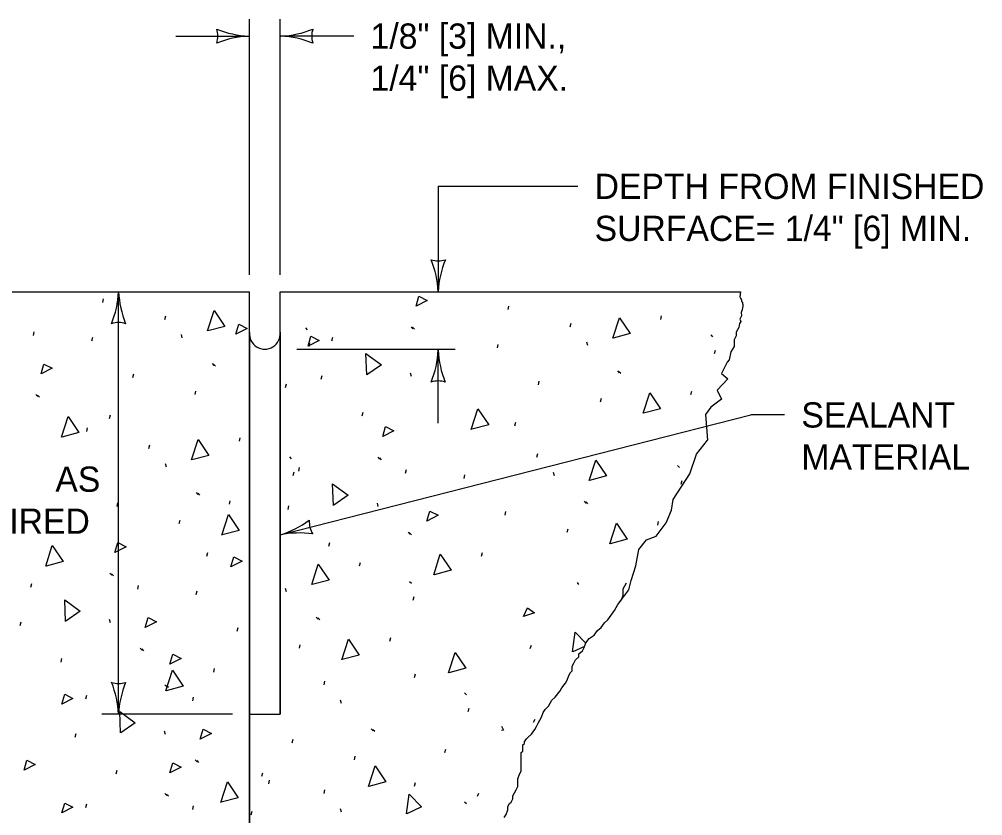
# Model space of a CAD drawing. Extents: x 49979.1 to 50021, y 49966.7 to 50011.4.
# Drawn here: x 50011.424 to 50013.716, y 49989.084 to 49990.977 of the extents above; entities that cross this region are included whole.
import ezdxf

# ---------------------------------------------------------------- set-up
doc = ezdxf.new("R2010")
doc.units = 0
for name, color, linetype in [('Level 1', 7, 'Continuous'), ('Level 12', 7, 'Continuous'), ('Level 13', 7, 'Continuous'), ('Level 2', 7, 'Continuous'), ('Level 3', 7, 'Continuous')]:
    doc.layers.add(name, color=color, linetype=linetype)

msp = doc.modelspace()

# ---------------------------------------------------------------- linework, layer by layer
at = {"layer": 'Level 1'}
for p, q in [((50010.8049, 49990.3296), (50011.972, 49990.3296)), ((50011.9717, 49989.3247), (50011.972, 49990.3296)), ((50012.0446, 49990.3296), (50013.1396, 49990.3296)), ((50012.0446, 49990.2334), (50012.0446, 49990.3296)), ((50011.972, 49990.2334), (50011.9714, 49988.4132)), ((50011.972, 49990.2334), (50011.972, 49990.2334)), ((50012.0446, 49989.3247), (50012.0446, 49990.2334)), ((50012.0446, 49990.2334), (50012.0446, 49989.3247))]:
    msp.add_line(p, q, dxfattribs=at)
for points in [[(50013.1396, 49990.3296), (50013.1383, 49990.3173), (50013.1403, 49990.3146), (50013.1403, 49990.3137), (50013.1413, 49990.3128), (50013.1413, 49990.3118), (50013.1413, 49990.3109), (50013.1424, 49990.31), (50013.1424, 49990.3091), (50013.1424, 49990.3082), (50013.1424, 49990.3073), (50013.1434, 49990.3054), (50013.1444, 49990.3045), (50013.1444, 49990.3036), (50013.1444, 49990.3027), (50013.1444, 49990.3018), (50013.1444, 49990.3008), (50013.1454, 49990.2999), (50013.1454, 49990.299), (50013.1454, 49990.2981), (50013.1454, 49990.2972), (50013.1454, 49990.2962), (50013.1454, 49990.2953), (50013.1437, 49990.2875), (50013.1437, 49990.2866), (50013.1427, 49990.2822), (50013.1414, 49990.2803), (50013.1427, 49990.272), (50013.1386, 49990.2641), (50013.1404, 49990.2586), (50013.1372, 49990.254), (50013.1363, 49990.2447), (50013.1298, 49990.2332), (50013.1298, 49990.2244), (50013.1252, 49990.2152), (50013.1252, 49990.199), (50013.1169, 49990.187), (50013.1132, 49990.1676), (50013.1081, 49990.162), (50013.095, 49990.1355), (50013.1099, 49990.1228), (50013.0843, 49990.0951), (50013.095, 49990.0738), (50013.0694, 49990.0547), (50013.0567, 49990.0376), (50013.0614, 49989.9766)], [(50012.6104, 49989.1712), (50012.6144, 49989.1823), (50012.6184, 49989.1896), (50012.6184, 49989.2006), (50012.6184, 49989.2116), (50012.6184, 49989.2226), (50012.6184, 49989.2263), (50012.6184, 49989.2336), (50012.6225, 49989.2373), (50012.6225, 49989.241), (50012.6225, 49989.2447), (50012.6225, 49989.2483), (50012.6225, 49989.252), (50012.6265, 49989.2557), (50012.6265, 49989.2593), (50012.6305, 49989.2667), (50012.6346, 49989.2704), (50012.6427, 49989.2777), (50012.6507, 49989.2887), (50012.6548, 49989.2961), (50012.6588, 49989.3034), (50012.6628, 49989.3107), (50012.6669, 49989.3181), (50012.6709, 49989.3291), (50012.675, 49989.3364), (50012.683, 49989.3438), (50012.6871, 49989.3511), (50012.6911, 49989.3585), (50012.6992, 49989.3658), (50012.7113, 49989.3805), (50012.7153, 49989.3878), (50012.7234, 49989.3988), (50012.7274, 49989.4062), (50012.7315, 49989.4172), (50012.7355, 49989.4245), (50012.7396, 49989.4282), (50012.7396, 49989.4319), (50012.7396, 49989.4392), (50012.7436, 49989.4466), (50012.7476, 49989.4539), (50012.7557, 49989.4612), (50012.7557, 49989.4686), (50012.7638, 49989.4759), (50012.7678, 49989.4833), (50012.7718, 49989.4943), (50012.7799, 49989.5053), (50012.792, 49989.5126), (50012.8001, 49989.5237), (50012.8082, 49989.531), (50012.8162, 49989.542), (50012.8243, 49989.5494), (50012.8324, 49989.5604), (50012.8405, 49989.5714), (50012.8485, 49989.5861), (50012.8743, 49989.6204), (50012.8799, 49989.6426), (50012.8909, 49989.6777), (50012.8983, 49989.7165), (50012.9162, 49989.7398), (50012.9396, 49989.7483), (50012.963, 49989.7802), (50012.9758, 49989.81), (50012.9801, 49989.8355), (50013.0194, 49989.8969), (50013.0353, 49989.9435), (50013.0614, 49989.9766)], [(50012.6104, 49989.1712), (50012.6144, 49989.1823), (50012.6184, 49989.1896), (50012.6184, 49989.2006), (50012.6184, 49989.2116), (50012.6184, 49989.2226), (50012.6184, 49989.2263), (50012.6184, 49989.2336), (50012.6225, 49989.2373), (50012.6225, 49989.241), (50012.6225, 49989.2447), (50012.6225, 49989.2483), (50012.6225, 49989.252), (50012.6265, 49989.2557), (50012.6265, 49989.2593), (50012.6305, 49989.2667), (50012.6346, 49989.2704), (50012.6427, 49989.2777), (50012.6507, 49989.2887), (50012.6548, 49989.2961), (50012.6588, 49989.3034), (50012.6628, 49989.3107), (50012.6669, 49989.3181), (50012.6709, 49989.3291), (50012.675, 49989.3364), (50012.683, 49989.3438), (50012.6871, 49989.3511), (50012.6911, 49989.3585), (50012.6992, 49989.3658), (50012.7113, 49989.3805), (50012.7153, 49989.3878), (50012.7234, 49989.3988), (50012.7274, 49989.4062), (50012.7315, 49989.4172), (50012.7355, 49989.4245), (50012.7396, 49989.4282), (50012.7396, 49989.4319), (50012.7396, 49989.4392), (50012.7436, 49989.4466), (50012.7476, 49989.4539), (50012.7557, 49989.4612), (50012.7557, 49989.4686), (50012.7638, 49989.4759), (50012.7678, 49989.4833), (50012.7718, 49989.4943), (50012.7799, 49989.5053), (50012.792, 49989.5126), (50012.8001, 49989.5237), (50012.8082, 49989.531), (50012.8162, 49989.542), (50012.8243, 49989.5494), (50012.8324, 49989.5604), (50012.8405, 49989.5714), (50012.8485, 49989.5861), (50012.8566, 49989.5971), (50012.8606, 49989.6081), (50012.8606, 49989.6228), (50012.8687, 49989.6374)], [(50011.9714, 49988.4132), (50011.9717, 49989.3247), (50012.0446, 49989.3247)], [(50012.5781, 49989.0795), (50012.5821, 49989.0868), (50012.5861, 49989.0978), (50012.5861, 49989.1052), (50012.5902, 49989.1125), (50012.5942, 49989.1162), (50012.5983, 49989.1235), (50012.5983, 49989.1309), (50012.6023, 49989.1382), (50012.6063, 49989.1455), (50012.6104, 49989.1529), (50012.6104, 49989.1639), (50012.6104, 49989.1712)]]:
    msp.add_lwpolyline(points, dxfattribs=at)
msp.add_arc((50012.0083, 49990.2295), 0.0365, 173.8329, 6.1791, dxfattribs=at)
at = {"layer": 'Level 12'}
for p, q in [((50012.716, 49989.3888), (50012.718, 49989.3932)), ((50011.908, 49989.3247), (50011.6655, 49989.3247))]:
    msp.add_line(p, q, dxfattribs=at)
at = {"layer": 'Level 13'}
for p, q in [((50011.6226, 49990.3042), (50011.6247, 49990.3127)), ((50012.587, 49990.287), (50012.5891, 49990.2955)), ((50011.7705, 49990.2635), (50011.7726, 49990.2719)), ((50012.9501, 49990.2634), (50012.9522, 49990.2719)), ((50012.7349, 49990.2462), (50012.737, 49990.2547)), ((50011.4579, 49990.2255), (50011.46, 49990.234)), ((50011.809, 49990.2278), (50011.8112, 49990.2201)), ((50012.1048, 49990.244), (50012.1093, 49990.2393)), ((50012.3562, 49990.2463), (50012.3606, 49990.2417)), ((50012.36, 49990.2449), (50012.3644, 49990.2403)), ((50013.0693, 49990.2267), (50013.0737, 49990.2221)), ((50011.5972, 49990.2131), (50011.5993, 49990.2216)), ((50012.1135, 49990.1995), (50012.1157, 49990.208)), ((50012.1681, 49990.2131), (50012.1702, 49990.2216)), ((50012.5616, 49990.1959), (50012.5637, 49990.2043)), ((50012.7734, 49990.2106), (50012.7757, 49990.2028)), ((50013.078, 49990.1823), (50013.0801, 49990.1908)), ((50011.8827, 49990.1588), (50011.8871, 49990.1542)), ((50011.8865, 49990.1575), (50011.8909, 49990.1528)), ((50011.6946, 49990.1257), (50011.6967, 49990.1342)), ((50012.3545, 49990.1367), (50012.3567, 49990.129)), ((50012.8471, 49990.1416), (50012.8515, 49990.137)), ((50012.8509, 49990.1402), (50012.8554, 49990.1356)), ((50012.0577, 49990.1021), (50012.0598, 49990.1106)), ((50012.1427, 49990.122), (50012.1448, 49990.1305)), ((50012.6591, 49990.1085), (50012.6612, 49990.1169)), ((50011.8425, 49990.0849), (50011.8446, 49990.0934)), ((50013.0221, 49990.0849), (50013.0242, 49990.0934)), ((50011.4638, 49990.085), (50011.4682, 49990.0803)), ((50011.4676, 49990.0836), (50011.472, 49990.079)), ((50012.8069, 49990.0677), (50012.809, 49990.0762)), ((50012.2402, 49990.0346), (50012.2423, 49990.0431)), ((50011.6388, 49990.0283), (50011.6409, 49990.0367)), ((50012.6032, 49990.011), (50012.6053, 49990.0195)), ((50011.5847, 49989.9975), (50011.5868, 49990.006)), ((50011.9478, 49989.9739), (50011.9499, 49989.9824)), ((50011.7326, 49989.9567), (50011.7347, 49989.9652)), ((50012.067, 49989.9372), (50012.0714, 49989.9326)), ((50012.2769, 49989.9361), (50012.2814, 49989.9315)), ((50012.2808, 49989.9347), (50012.2852, 49989.9301)), ((50012.6557, 49989.936), (50012.6578, 49989.9445)), ((50011.7711, 49989.9211), (50011.7733, 49989.9133)), ((50012.0889, 49989.903), (50012.091, 49989.9114)), ((50012.3431, 49989.8981), (50012.3452, 49989.9066)), ((50012.99, 49989.9166), (50012.9945, 49989.9119)), ((50012.0757, 49989.8928), (50012.0778, 49989.9013)), ((50012.4824, 49989.8857), (50012.4845, 49989.8942)), ((50012.6942, 49989.9004), (50012.6964, 49989.8927)), ((50012.9988, 49989.8721), (50013.0009, 49989.8806)), ((50011.8448, 49989.8521), (50011.8492, 49989.8475)), ((50011.8486, 49989.8507), (50011.8531, 49989.8461)), ((50011.6567, 49989.819), (50011.6589, 49989.8274)), ((50011.9242, 49989.8242), (50011.9263, 49989.8327)), ((50012.0635, 49989.8118), (50012.0656, 49989.8203)), ((50012.2753, 49989.8265), (50012.2775, 49989.8188)), ((50012.7679, 49989.8314), (50012.7723, 49989.8268)), ((50012.7717, 49989.8301), (50012.7761, 49989.8254)), ((50012.5798, 49989.7983), (50012.582, 49989.8068)), ((50011.8046, 49989.7782), (50011.8067, 49989.7867)), ((50012.7277, 49989.7575), (50012.7298, 49989.766)), ((50012.9429, 49989.7747), (50012.945, 49989.7832)), ((50012.349, 49989.7576), (50012.3534, 49989.7529)), ((50012.3528, 49989.7562), (50012.3572, 49989.7516)), ((50012.1609, 49989.7244), (50012.163, 49989.7329)), ((50011.8706, 49989.7011), (50011.8727, 49989.7096)), ((50012.524, 49989.7008), (50012.5261, 49989.7093)), ((50012.2337, 49989.6775), (50012.2358, 49989.686)), ((50011.6397, 49989.6604), (50011.6441, 49989.6558)), ((50011.6436, 49989.659), (50011.648, 49989.6544)), ((50011.4517, 49989.6272), (50011.4538, 49989.6357)), ((50011.7059, 49989.6224), (50011.708, 49989.6309)), ((50012.3528, 49989.6408), (50012.3573, 49989.6362)), ((50012.751, 49989.638), (50012.7543, 49989.6331)), ((50011.8452, 49989.61), (50011.8473, 49989.6185)), ((50012.057, 49989.6247), (50012.0592, 49989.617)), ((50012.3615, 49989.5964), (50012.3637, 49989.6049)), ((50011.4263, 49989.5361), (50011.4284, 49989.5446)), ((50011.638, 49989.5508), (50011.6403, 49989.5431)), ((50012.1307, 49989.5557), (50012.1351, 49989.5511)), ((50012.1345, 49989.5543), (50012.1389, 49989.5497)), ((50011.9426, 49989.5226), (50011.9447, 49989.5311)), ((50012.3057, 49989.499), (50012.3078, 49989.5075)), ((50011.7117, 49989.4819), (50011.7162, 49989.4772)), ((50011.7156, 49989.4805), (50011.72, 49989.4758)), ((50012.0905, 49989.4818), (50012.0926, 49989.4903)), ((50012.6397, 49989.4814), (50012.643, 49989.4889)), ((50011.5237, 49989.4487), (50011.5258, 49989.4572)), ((50011.8868, 49989.4251), (50011.8889, 49989.4336)), ((50012.1493, 49989.395), (50012.1515, 49989.4035)), ((50012.3645, 49989.4122), (50012.3667, 49989.4207)), ((50011.7706, 49989.395), (50011.775, 49989.3904)), ((50011.7745, 49989.3936), (50011.7789, 49989.389)), ((50011.5826, 49989.3619), (50011.5847, 49989.3704)), ((50011.8368, 49989.357), (50011.8389, 49989.3655)), ((50012.1878, 49989.3593), (50012.1901, 49989.3516)), ((50012.4837, 49989.3755), (50012.4881, 49989.3708)), ((50012.4924, 49989.3311), (50012.4945, 49989.3395)), ((50012.6479, 49989.3058), (50012.6512, 49989.3132)), ((50011.7689, 49989.2854), (50011.7712, 49989.2777)), ((50012.2615, 49989.2903), (50012.266, 49989.2857)), ((50012.2654, 49989.289), (50012.2698, 49989.2843)), ((50011.5571, 49989.2707), (50011.5592, 49989.2792)), ((50012.0735, 49989.2572), (50012.0756, 49989.2657)), ((50012.4366, 49989.2336), (50012.4387, 49989.2421)), ((50011.8426, 49989.2165), (50011.8471, 49989.2118)), ((50012.2214, 49989.2164), (50012.2235, 49989.2249)), ((50011.8465, 49989.2151), (50011.8509, 49989.2105)), ((50011.6546, 49989.1833), (50011.6567, 49989.1918)), ((50012.0015, 49989.1773), (50012.0036, 49989.1857)), ((50012.0177, 49989.1598), (50012.0198, 49989.1682)), ((50012.3645, 49989.1537), (50012.3667, 49989.1622)), ((50011.7706, 49989.1365), (50011.775, 49989.1319)), ((50011.7745, 49989.1352), (50011.7789, 49989.1305)), ((50012.1493, 49989.1365), (50012.1515, 49989.145)), ((50012.5144, 49989.1302), (50012.5177, 49989.1376)), ((50011.5826, 49989.1034), (50011.5847, 49989.1119)), ((50011.8368, 49989.0985), (50011.8389, 49989.107)), ((50012.4837, 49989.117), (50012.4881, 49989.1124)), ((50011.976, 49989.0861), (50011.9782, 49989.0946)), ((50012.1878, 49989.1008), (50012.1901, 49989.0931))]:
    msp.add_line(p, q, dxfattribs=at)
for points in [[(50012.3683, 49990.2953), (50012.3749, 49990.319), (50012.3947, 49990.309), (50012.3683, 49990.2953)], [(50011.8718, 49990.2362), (50011.8875, 49990.285), (50011.9131, 49990.2471), (50011.8726, 49990.2364)], [(50011.9397, 49990.2286), (50011.9463, 49990.2523), (50011.9661, 49990.2422), (50011.9397, 49990.2286)], [(50012.8362, 49990.219), (50012.8519, 49990.2678), (50012.8776, 49990.2299), (50012.8371, 49990.2192)], [(50012.1111, 49990.1999), (50012.1177, 49990.2236), (50012.1375, 49990.2135), (50012.1111, 49990.1999)], [(50012.2507, 49990.1317), (50012.2488, 49990.1829), (50012.2858, 49990.1561), (50012.2514, 49990.1322)], [(50011.4759, 49990.134), (50011.4825, 49990.1577), (50011.5023, 49990.1477), (50011.4759, 49990.134)], [(50012.9082, 49990.0405), (50012.924, 49990.0892), (50012.9496, 49990.0514), (50012.9091, 49990.0406)], [(50012.4996, 49990.0023), (50012.5154, 49990.051), (50012.541, 49990.0132), (50012.5005, 49990.0024)], [(50011.5249, 49989.9838), (50011.5406, 49990.0326), (50011.5662, 49989.9947), (50011.5258, 49989.984)], [(50012.289, 49989.9851), (50012.2957, 49990.0088), (50012.3155, 49989.9988), (50012.289, 49989.9851)], [(50011.8339, 49989.9295), (50011.8496, 49989.9783), (50011.8752, 49989.9404), (50011.8347, 49989.9297)], [(50012.7798, 49989.8805), (50012.7955, 49989.9292), (50012.8211, 49989.8914), (50012.7806, 49989.8806)], [(50012.1715, 49989.8215), (50012.1696, 49989.8727), (50012.2066, 49989.8459), (50012.1722, 49989.822)], [(50011.9059, 49989.751), (50011.9217, 49989.7997), (50011.9473, 49989.7619), (50011.9068, 49989.7511)], [(50012.394, 49989.7842), (50012.4006, 49989.8079), (50012.4204, 49989.7979), (50012.394, 49989.7842)], [(50012.829, 49989.7303), (50012.8447, 49989.779), (50012.8704, 49989.7412), (50012.8299, 49989.7304)], [(50011.487, 49989.6771), (50011.5027, 49989.7259), (50011.5284, 49989.688), (50011.4879, 49989.6772)], [(50011.6518, 49989.7094), (50011.6585, 49989.7331), (50011.6783, 49989.7231), (50011.6518, 49989.7094)], [(50011.9278, 49989.6751), (50011.9344, 49989.6988), (50011.9542, 49989.6888), (50011.9278, 49989.6751)], [(50012.4101, 49989.6564), (50012.4258, 49989.7052), (50012.4514, 49989.6673), (50012.411, 49989.6566)], [(50012.1198, 49989.6331), (50012.1355, 49989.6819), (50012.1611, 49989.644), (50012.1206, 49989.6333)], [(50011.5342, 49989.5458), (50011.5324, 49989.597), (50011.5694, 49989.5702), (50011.535, 49989.5463)], [(50012.6234, 49989.5577), (50012.6332, 49989.5783), (50012.6498, 49989.5659), (50012.6234, 49989.5577)], [(50011.7239, 49989.5309), (50011.7305, 49989.5546), (50011.7503, 49989.5446), (50011.7239, 49989.5309)], [(50012.74, 49989.4729), (50012.7465, 49989.52), (50012.7717, 49989.494)], [(50012.1918, 49989.4546), (50012.2075, 49989.5033), (50012.2331, 49989.4655), (50012.1927, 49989.4547)], [(50012.4454, 49989.4232), (50012.4612, 49989.4719), (50012.4868, 49989.4341), (50012.4463, 49989.4233)], [(50012.7689, 49989.4862), (50012.7407, 49989.4732)], [(50011.7827, 49989.444), (50011.7893, 49989.4678), (50011.8092, 49989.4577), (50011.7827, 49989.444)], [(50011.7729, 49989.3807), (50011.7886, 49989.4295), (50011.8142, 49989.3916), (50011.7738, 49989.3809)], [(50011.5256, 49989.3486), (50011.5322, 49989.3723), (50011.552, 49989.3623), (50011.5256, 49989.3486)], [(50011.6651, 49989.2804), (50011.6632, 49989.3317), (50011.7003, 49989.3048), (50011.6659, 49989.2809)], [(50011.8547, 49989.2655), (50011.8614, 49989.2892), (50011.8812, 49989.2792), (50011.8547, 49989.2655)], [(50012.5717, 49989.2969), (50012.5762, 49989.2868), (50012.5717, 49989.2864)], [(50011.4358, 49989.1916), (50011.4425, 49989.2154), (50011.4623, 49989.2053), (50011.4358, 49989.1916)], [(50011.7827, 49989.1856), (50011.7893, 49989.2093), (50011.8092, 49989.1992), (50011.7827, 49989.1856)], [(50012.255, 49989.1532), (50012.2707, 49989.202), (50012.2963, 49989.1641), (50012.2559, 49989.1534)], [(50011.9038, 49989.1153), (50011.9195, 49989.1641), (50011.9451, 49989.1262), (50011.9046, 49989.1155)], [(50012.3451, 49989.0879), (50012.3517, 49989.135), (50012.3812, 49989.1045), (50012.3459, 49989.0882)], [(50011.5256, 49989.0901), (50011.5322, 49989.1138), (50011.552, 49989.1038), (50011.5256, 49989.0901)]]:
    msp.add_lwpolyline(points, dxfattribs=at)
at = {"layer": 'Level 3'}
for p, q in [((50011.972, 49990.3696), (50011.972, 49990.9774)), ((50012.0446, 49990.3696), (50012.0446, 49990.9774)), ((50011.7967, 49990.9374), (50011.972, 49990.9374)), ((50012.2199, 49990.9374), (50012.0446, 49990.9374)), ((50012.4209, 49990.5802), (50012.4209, 49990.3296)), ((50012.4209, 49990.5802), (50012.7529, 49990.5802)), ((50011.6605, 49989.3247), (50011.6605, 49990.3296)), ((50012.0846, 49990.1926), (50012.4609, 49990.1926)), ((50012.4209, 49990.0173), (50012.4209, 49990.1926)), ((50012.0446, 49989.7511), (50013.1648, 49990.0366)), ((50013.2448, 49990.0366), (50013.1648, 49990.0366)), ((50011.9317, 49989.3247), (50011.6205, 49989.3247))]:
    msp.add_line(p, q, dxfattribs=at)
for centre, radius, start, end in [((50011.9793, 49991.1595), 0.2223, 247.456, 267.6395), ((50011.8419, 49990.9374), 0.0548, 342.1388, 17.8612), ((50011.9816, 49990.7047), 0.233, 92.8273, 112.0772), ((50012.0373, 49991.1595), 0.2223, 272.3605, 292.544), ((50012.035, 49990.7047), 0.233, 67.9228, 87.1727), ((50012.1747, 49990.9374), 0.0548, 162.1388, 197.8612), ((50012.4209, 49990.4578), 0.0548, 252.1388, 287.8612), ((50012.1882, 49990.3181), 0.233, 2.8273, 22.0772), ((50012.6431, 49990.3204), 0.2223, 157.456, 177.6395), ((50011.4383, 49990.3387), 0.2223, 337.456, 357.6395), ((50011.8932, 49990.3411), 0.233, 182.8273, 202.0772), ((50011.6605, 49990.2014), 0.0548, 72.1388, 107.8612), ((50012.1881, 49990.2022), 0.233, 337.9228, 357.1727), ((50012.643, 49990.1999), 0.2223, 182.3605, 202.544), ((50012.4209, 49990.0625), 0.0548, 72.1388, 107.8612), ((50011.976, 49989.9738), 0.233, 287.1287, 306.3785), ((50012.1689, 49989.7828), 0.0548, 176.4402, 212.1625), ((50012.0906, 49989.5336), 0.2223, 81.7574, 101.9409), ((50011.6605, 49989.4529), 0.0548, 252.1388, 287.8612), ((50011.4278, 49989.3132), 0.233, 2.8273, 22.0772), ((50011.8826, 49989.3155), 0.2223, 157.456, 177.6395)]:
    msp.add_arc(centre, radius, start, end, dxfattribs=at)

# ---------------------------------------------------------------- texts
at = {"layer": 'Level 2'}
for s, p in [('1/8" [3] MIN.,', (50012.2599, 49990.9074)), ('1/4" [6] MAX.', (50012.2599, 49990.8074)), ('DEPTH FROM FINISHED ', (50012.7929, 49990.5502)), ('SURFACE= 1/4" [6] MIN.', (50012.7929, 49990.4502)), ('SEALANT ', (50013.2848, 49990.0066)), ('MATERIAL', (50013.2848, 49989.9066))]:
    msp.add_text(s, height=0.06, dxfattribs=at).set_placement(p)
for s, p in [('AS ', (50011.51, 49989.8539)), ('REQUIRED', (50011.1686, 49989.7539))]:
    msp.add_text(s, height=0.06, rotation=360, dxfattribs=at).set_placement(p)

doc.saveas('drawing.dxf')
